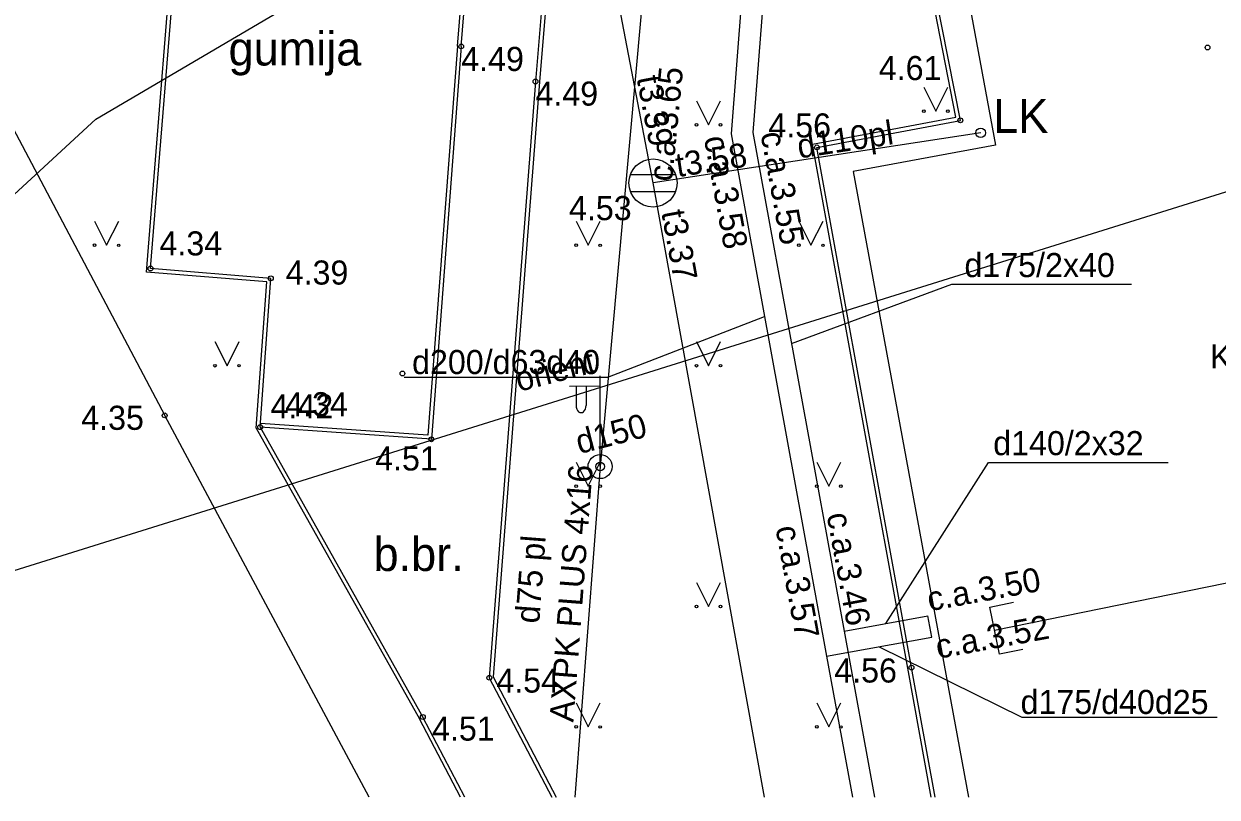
# Model space of a CAD drawing. Extents: x 484635 to 484808, y 278866 to 278977.
# Drawn here: x 484755.78 to 484780.57, y 278866.04 to 278882.1 of the extents above; entities that cross this region are included whole.
import ezdxf

# ---------------------------------------------------------------- set-up
doc = ezdxf.new("R2010")
doc.units = 0
for name, color, linetype in [('APGS_ACRL_####_####_#', 7, 'Continuous'), ('APGS_ACRL_####_TKST_#', 7, 'Continuous'), ('APGS_ELEM_####_####_#', 7, 'Continuous'), ('APGS_ELEM_####_TKST_#', 7, 'Continuous'), ('APGS_VADP_ZSPR_####_I', 7, 'Continuous'), ('APGS_VADP_ZSPR_TKST_I', 7, 'Continuous'), ('BUVE_EKAS_####_####_#', 7, 'Continuous'), ('CELI_CAPM_####_####_#', 7, 'Continuous'), ('CELI_CSEG_####_TKST_#', 7, 'Continuous'), ('ELEK_ELEM_####_TKST_#', 7, 'Continuous'), ('LKAN_ELEM_####_####_#', 7, 'Continuous'), ('LKAN_ELEM_PAST_TKST_#', 7, 'Continuous'), ('LKAN_VADP_PAST_####_#', 7, 'Continuous'), ('LKAN_VADP_PAST_####_I', 7, 'Continuous'), ('LKAN_VADP_PAST_TKST_I', 7, 'Continuous'), ('NORB_ZOGS_ZSTP_####_#', 7, 'Continuous'), ('RELJ_AATZ_####_TKST_#', 7, 'Continuous'), ('RELJ_ELEM_####_####_#', 7, 'Continuous'), ('SILT_VADP_UDEN_####_I', 7, 'Continuous'), ('SILT_VADP_UDEN_TKST_I', 7, 'Continuous'), ('SKAN_VADP_NEDR_####_#', 7, 'Continuous'), ('SKAN_VADP_SPDK_TKST_#', 7, 'Continuous'), ('TERT_ELEM_####_####_#', 7, 'Continuous'), ('UDTK_ELEM_####_####_#', 7, 'Continuous'), ('UDTK_VADP_NEDR_####_#', 7, 'Continuous'), ('UDTK_VADP_UDEN_####_I', 7, 'Continuous'), ('UDTK_VADP_UDEN_TKST_I', 7, 'Continuous')]:
    doc.layers.add(name, color=color, linetype=linetype)

msp = doc.modelspace()

# ---------------------------------------------------------------- linework, layer by layer
at = {"layer": 'APGS_ACRL_####_####_#'}
msp.add_lwpolyline([(484777.807, 278900.58), (484777.114, 278898.745), (484769.642, 278893.153), (484768.844, 278885.007), (484767.749, 278872.905), (484767.227, 278866.043)], dxfattribs=at)
at = {"layer": 'APGS_ELEM_####_####_#'}
for p, q in [((484767.749, 278872.905), (484767.749, 278874.788)), ((484767.749, 278874.572), (484767.114, 278874.567)), ((484767.249, 278874.568), (484767.249, 278874.176)), ((484767.459, 278874.57), (484767.459, 278874.176))]:
    msp.add_line(p, q, dxfattribs=at)
for radius in [0.25, 0.09]:
    msp.add_circle((484767.749, 278872.905), radius, dxfattribs=at)
msp.add_ellipse((484767.354, 278874.176), major_axis=(0, 0.151), ratio=0.695971, start_param=1.570796, end_param=4.712389, dxfattribs=at)
at = {"layer": 'APGS_VADP_ZSPR_####_I'}
msp.add_lwpolyline([(484777.807, 278900.58), (484777.114, 278898.745), (484769.642, 278893.153), (484768.844, 278885.007), (484767.749, 278872.905), (484767.227, 278866.043)], dxfattribs=at)
at = {"layer": 'BUVE_EKAS_####_####_#'}
for p, q in [((484773.318, 278893.935), (484775.96, 278879.576)), ((484775.96, 278879.576), (484773.009, 278879.033)), ((484773.009, 278879.033), (484775.399, 278866.043))]:
    msp.add_line(p, q, dxfattribs=at)
at = {"layer": 'CELI_CAPM_####_####_#'}
for p, q in [((484758.324, 278876.945), (484759.228, 278888.066)), ((484764.786, 278881.634), (484765.319, 278888.086)), ((484764.865, 278881.628), (484765.396, 278888.056)), ((484758.41, 278877.018), (484759.301, 278887.98)), ((484766.957, 278887.466), (484766.407, 278880.899)), ((484767.035, 278887.437), (484766.487, 278880.893)), ((484775.138, 278880.157), (484773.902, 278886.466)), ((484775.232, 278880.093), (484773.981, 278886.482)), ((484766.407, 278880.899), (484765.448, 278868.521)), ((484766.487, 278880.893), (484765.53, 278868.538)), ((484772.159, 278879.596), (484775.138, 278880.157)), ((484772.252, 278879.532), (484775.232, 278880.093)), ((484774.14, 278868.719), (484772.159, 278879.596)), ((484774.218, 278868.733), (484772.252, 278879.532)), ((484760.825, 278876.739), (484758.324, 278876.945)), ((484760.91, 278876.813), (484758.41, 278877.018)), ((484760.608, 278873.705), (484760.825, 278876.739)), ((484760.689, 278873.723), (484760.91, 278876.813)), ((484764.244, 278873.472), (484760.689, 278873.723)), ((484764.17, 278873.557), (484760.695, 278873.803)), ((484774.627, 278866.043), (484774.14, 278868.719)), ((484774.709, 278866.043), (484774.218, 278868.733)), ((484765.448, 278868.521), (484766.747, 278866.043)), ((484765.53, 278868.538), (484766.838, 278866.043)), ((484764.939, 278866.043), (484764.067, 278867.706)), ((484764.848, 278866.043), (484763.996, 278867.669))]:
    msp.add_line(p, q, dxfattribs=at)
for points in [[(484764.786, 278881.634), (484764.17, 278873.557)], [(484764.865, 278881.628), (484764.244, 278873.472)], [(484760.608, 278873.705), (484763.997, 278867.667)], [(484760.689, 278873.723), (484764.067, 278867.706)]]:
    msp.add_lwpolyline(points, dxfattribs=at)
at = {"layer": 'LKAN_ELEM_####_####_#'}
for p, q in [((484768.38, 278878.968), (484769.316, 278878.968)), ((484768.38, 278878.618), (484769.316, 278878.618))]:
    msp.add_line(p, q, dxfattribs=at)
for centre, radius in [((484775.654, 278879.834), 0.1), ((484768.848, 278878.793), 0.5)]:
    msp.add_circle(centre, radius, dxfattribs=at)
at = {"layer": 'LKAN_VADP_PAST_####_#'}
for points in [[(484768.848, 278878.793), (484767.006, 278888.444)], [(484771.167, 278866.043), (484768.848, 278878.793)]]:
    msp.add_lwpolyline(points, dxfattribs=at)
at = {"layer": 'LKAN_VADP_PAST_####_I'}
msp.add_lwpolyline([(484775.654, 278879.834), (484768.848, 278878.793)], dxfattribs=at)
at = {"layer": 'NORB_ZOGS_ZSTP_####_#'}
msp.add_line((484752.851, 278885.041), (484758.705, 278873.968), dxfattribs=at)
msp.add_lwpolyline([(484762.955, 278866.043), (484758.705, 278873.968)], dxfattribs=at)
at = {"layer": 'RELJ_ELEM_####_####_#'}
for centre in [(484764.865, 278881.628), (484780.367, 278881.605), (484766.407, 278880.899), (484775.232, 278880.093), (484772.252, 278879.532), (484758.41, 278877.018), (484760.91, 278876.813), (484763.643, 278874.838), (484758.705, 278873.968), (484760.689, 278873.723), (484764.244, 278873.472), (484774.218, 278868.733), (484765.448, 278868.521), (484764.067, 278867.706)]:
    msp.add_circle(centre, 0.05, dxfattribs=at)
at = {"layer": 'SILT_VADP_UDEN_####_I'}
msp.add_line((484772.816, 278869.49), (484773.447, 278866.043), dxfattribs=at)
for points in [[(484774.92, 278884.42), (484771.223, 278883.74), (484770.922, 278879.839), (484772.816, 278869.49)], [(484772.816, 278869.49), (484774.557, 278869.808)]]:
    msp.add_lwpolyline(points, dxfattribs=at)
at = {"layer": 'SILT_VADP_UDEN_TKST_I'}
for points in [[(484771.724, 278875.459), (484775.053, 278876.689), (484778.789, 278876.689)], [(484773.687, 278869.649), (484775.814, 278872.992), (484779.55, 278872.992)]]:
    msp.add_lwpolyline(points, dxfattribs=at)
at = {"layer": 'SKAN_VADP_NEDR_####_#'}
for points in [[(484756.132, 278870.921), (484807.573, 278886.997)], [(484740.521, 278866.043), (484756.132, 278870.921)]]:
    msp.add_lwpolyline(points, dxfattribs=at)
at = {"layer": 'TERT_ELEM_####_####_#'}
for p, q in [((484774.473, 278880.784), (484774.723, 278880.284)), ((484774.723, 278880.284), (484774.973, 278880.784)), ((484769.75, 278880.5), (484770, 278880)), ((484770, 278880), (484770.25, 278880.5)), ((484757.25, 278878), (484757.5, 278877.5)), ((484757.5, 278877.5), (484757.75, 278878)), ((484767.25, 278878), (484767.5, 278877.5)), ((484767.5, 278877.5), (484767.75, 278878)), ((484771.879, 278878), (484772.129, 278877.5)), ((484772.129, 278877.5), (484772.379, 278878)), ((484759.75, 278875.5), (484760, 278875)), ((484760, 278875), (484760.25, 278875.5)), ((484769.75, 278875.5), (484770, 278875)), ((484770, 278875), (484770.25, 278875.5)), ((484767.25, 278873), (484767.5, 278872.5)), ((484767.5, 278872.5), (484767.75, 278873)), ((484772.25, 278873), (484772.5, 278872.5)), ((484772.5, 278872.5), (484772.75, 278873)), ((484769.75, 278870.5), (484770, 278870)), ((484770, 278870), (484770.25, 278870.5)), ((484767.25, 278868), (484767.5, 278867.5)), ((484767.5, 278867.5), (484767.75, 278868)), ((484772.25, 278868), (484772.5, 278867.5)), ((484772.5, 278867.5), (484772.75, 278868))]:
    msp.add_line(p, q, dxfattribs=at)
for centre, radius in [((484774.473, 278880.283), 0.028), ((484774.973, 278880.283), 0.0263), ((484769.75, 278880), 0.028), ((484770.25, 278880), 0.0263), ((484757.25, 278877.5), 0.028), ((484757.75, 278877.5), 0.0263), ((484767.25, 278877.5), 0.028), ((484767.75, 278877.5), 0.0263), ((484771.878, 278877.5), 0.028), ((484772.378, 278877.5), 0.0263), ((484759.75, 278875), 0.028), ((484760.25, 278875), 0.0263), ((484769.75, 278875), 0.028), ((484770.25, 278875), 0.0263), ((484767.25, 278872.5), 0.028), ((484767.75, 278872.5), 0.0263), ((484772.25, 278872.5), 0.028), ((484772.75, 278872.5), 0.0263), ((484769.75, 278870), 0.028), ((484770.25, 278870), 0.0263), ((484767.25, 278867.5), 0.028), ((484767.75, 278867.5), 0.0263), ((484772.25, 278867.5), 0.028), ((484772.75, 278867.5), 0.0263)]:
    msp.add_circle(centre, radius, dxfattribs=at)
at = {"layer": 'UDTK_ELEM_####_####_#'}
msp.add_lwpolyline([(484776.533, 278869.11), (484776.043, 278869.01), (484775.843, 278869.99), (484776.333, 278870.09)], dxfattribs=at)
at = {"layer": 'UDTK_VADP_NEDR_####_#'}
msp.add_lwpolyline([(484753.238, 278876.403), (484757.275, 278880.118), (484799.521, 278904.942)], dxfattribs=at)
at = {"layer": 'UDTK_VADP_UDEN_####_I'}
msp.add_line((484772.455, 278868.966), (484772.99, 278866.043), dxfattribs=at)
for points in [[(484774.839, 278884.862), (484770.801, 278884.12), (484770.469, 278879.816), (484772.455, 278868.966)], [(484807.573, 278875.943), (484775.943, 278869.5)], [(484772.455, 278868.966), (484774.638, 278869.366)]]:
    msp.add_lwpolyline(points, dxfattribs=at)
at = {"layer": 'UDTK_VADP_UDEN_TKST_I'}
msp.add_line((484774.638, 278869.366), (484774.557, 278869.808), dxfattribs=at)
for points in [[(484763.68, 278874.762), (484767.909, 278874.762), (484771.164, 278876.02)], [(484773.546, 278869.166), (484776.506, 278867.701), (484780.563, 278867.701)]]:
    msp.add_lwpolyline(points, dxfattribs=at)

# ---------------------------------------------------------------- texts
at = {"layer": 'APGS_ACRL_####_TKST_#'}
msp.add_text('d75 pl', height=0.5, rotation=85.6507, dxfattribs=at).set_placement((484766.483, 278869.639))
at = {"layer": 'APGS_ELEM_####_TKST_#'}
msp.add_text('c.a.3.65', height=0.5, rotation=84.4033, dxfattribs=at).set_placement((484769.244, 278878.811))
at = {"layer": 'APGS_VADP_ZSPR_TKST_I'}
msp.add_text('AXPK PLUS 4x16', height=0.5, rotation=85.6507, dxfattribs=at).set_placement((484767.194, 278867.589))
at = {"layer": 'CELI_CSEG_####_TKST_#'}
for s, p in [('gumija', (484760.031, 278881.233)), ('b.br.', (484763.043, 278870.738))]:
    msp.add_text(s, height=0.7, dxfattribs=at).set_placement(p)
at = {"layer": 'ELEK_ELEM_####_TKST_#'}
msp.add_text('K366838', height=0.5, dxfattribs=at).set_placement((484780.421, 278874.943))
at = {"layer": 'LKAN_ELEM_####_####_#'}
msp.add_text(' LK', height=0.7, dxfattribs=at).set_placement((484775.654, 278879.834))
at = {"layer": 'LKAN_ELEM_PAST_TKST_#'}
msp.add_text('4.53', height=0.5, dxfattribs=at).set_placement((484767.103, 278878.021))
at = {"layer": 'LKAN_VADP_PAST_TKST_I'}
for s, rotation, p in [('t3.39', 280.8009, (484768.505, 278880.976)), ('d110pl', 8.6995, (484771.884, 278879.3)), ('t3.58', 8.6995, (484769.359, 278878.914)), ('t3.37', 280.3121, (484769.02, 278878.19))]:
    msp.add_text(s, height=0.5, rotation=rotation, dxfattribs=at).set_placement(p)
at = {"layer": 'RELJ_AATZ_####_TKST_#'}
for s, p in [('4.49', (484764.865, 278881.118)), ('4.61', (484773.538, 278880.929)), ('4.49', (484766.407, 278880.399)), ('4.56', (484771.244, 278879.738)), ('4.34', (484758.598, 278877.289)), ('4.39', (484761.219, 278876.684)), ('4.42', (484760.904, 278873.907)), (' 4.34', (484761.022, 278873.95)), ('4.35', (484756.972, 278873.668)), ('4.51', (484763.077, 278872.824)), ('4.54', (484765.594, 278868.213)), ('4.56', (484772.613, 278868.422)), ('4.51', (484764.259, 278867.216))]:
    msp.add_text(s, height=0.5, dxfattribs=at).set_placement(p)
at = {"layer": 'SILT_VADP_UDEN_TKST_I'}
for s, rotation, p in [('c.a.3.55', 280.3713, (484771.079, 278879.818)), ('c.a.3.46', 280.3713, (484772.453, 278871.909)), ('c.a.3.50', 10.3797, (484774.592, 278869.901))]:
    msp.add_text(s, height=0.5, rotation=rotation, dxfattribs=at).set_placement(p)
for s, p in [('d175/2x40', (484775.317, 278876.839)), ('d140/2x32', (484775.915, 278873.142))]:
    msp.add_text(s, height=0.5, dxfattribs=at).set_placement(p)
at = {"layer": 'SKAN_VADP_SPDK_TKST_#'}
for s, p in [('orient', (484766.062, 278874.456)), ('d150', (484767.318, 278873.163))]:
    msp.add_text(s, height=0.5, rotation=14.4118, dxfattribs=at).set_placement(p)
at = {"layer": 'UDTK_VADP_UDEN_TKST_I'}
for s, rotation, p in [('c.a.3.58', 280.3713, (484769.903, 278879.73)), ('c.a.3.57', 280.3713, (484771.389, 278871.637)), ('c.a.3.52', 10.3797, (484774.769, 278868.913))]:
    msp.add_text(s, height=0.5, rotation=rotation, dxfattribs=at).set_placement(p)
for s, p in [('d200/d63d40', (484763.844, 278874.826)), ('d175/d40d25', (484776.483, 278867.769))]:
    msp.add_text(s, height=0.5, dxfattribs=at).set_placement(p)

doc.saveas('drawing.dxf')
